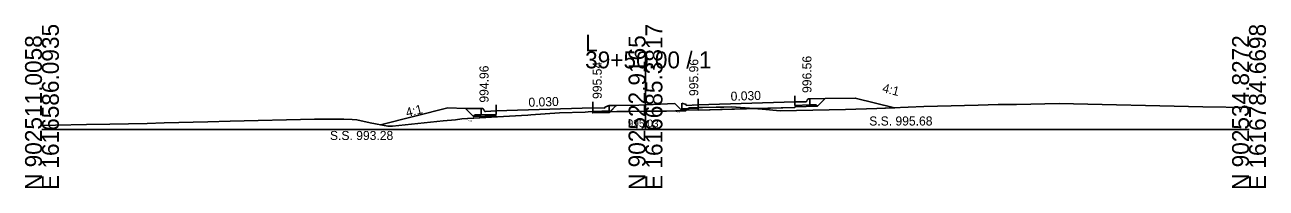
# Model space of a CAD drawing. Extents: x 1009 to 7438, y -1586 to 7964.
# Drawn here: x 3032.1 to 3237.7, y 7414 to 7441.1 of the extents above; entities that cross this region are included whole.
import ezdxf

# ---------------------------------------------------------------- set-up
doc = ezdxf.new("R2010")
doc.units = 0
for name, color, linetype in [('Exist Cross Section Cell', 7, 'Continuous'), ('Exist XS Center Line Elevation Label', 7, 'Continuous'), ('Exist XS Ground Line', 7, 'Continuous'), ('Prop XS Dump Level', 7, 'Continuous'), ('Prop XS Earthwork Shape', 7, 'Continuous'), ('Prop XS EOT Tick Mark', 7, 'Continuous'), ('Prop XS Finish Grade', 7, 'Continuous'), ('Prop XS Finish Grade CurbGutter', 7, 'Continuous'), ('Prop XS Finish Grade Earthwork', 7, 'Continuous'), ('Prop XS Finish Grade Pavement', 7, 'Continuous'), ('Prop XS Hydro Elevations', 7, 'Continuous'), ('Prop XS Pvmt Edge Slope', 7, 'Continuous'), ('Prop XS SE Text', 7, 'Continuous'), ('Prop XS Side Slope Text', 7, 'Continuous'), ('Prop XS SS Elevation Text', 7, 'Continuous'), ('Prop XS Subgrade CurbGutter', 7, 'Continuous'), ('Prop XS Subgrade Earthwork', 7, 'Continuous')]:
    doc.layers.add(name, color=color, linetype=linetype)

msp = doc.modelspace()

# ---------------------------------------------------------------- linework, layer by layer
at = {"layer": 'Exist Cross Section Cell'}
for p, q in [((3134.89, 7423.73), (3134.89, 7436.66)), ((3034.89, 7423.73), (3134.89, 7423.73)), ((3134.89, 7423.73), (3234.89, 7423.73))]:
    msp.add_line(p, q, dxfattribs=at)
at = {"layer": 'Exist XS Ground Line'}
for p, q in [((3141.5, 7426.85), (3142.15, 7427.33)), ((3142.15, 7427.33), (3146.62, 7427.42)), ((3146.62, 7427.42), (3147.17, 7427.43)), ((3147.17, 7427.43), (3147.85, 7427.45)), ((3147.85, 7427.45), (3149.14, 7427.47)), ((3149.14, 7427.47), (3154.22, 7427.1)), ((3168.02, 7427.07), (3173.2, 7427.2)), ((3173.2, 7427.2), (3181.03, 7427.53)), ((3181.03, 7427.53), (3183.27, 7427.61)), ((3183.27, 7427.61), (3190.02, 7427.79)), ((3190.02, 7427.79), (3193.34, 7427.86)), ((3193.34, 7427.86), (3196.34, 7427.88)), ((3196.34, 7427.88), (3203.41, 7428.04)), ((3203.41, 7428.04), (3227.22, 7427.5)), ((3227.22, 7427.5), (3234.89, 7427.37)), ((3062.4, 7425.03), (3066.06, 7425.12)), ((3066.06, 7425.12), (3080.03, 7425.47)), ((3080.03, 7425.47), (3083.82, 7425.45)), ((3083.82, 7425.45), (3084.91, 7425.44)), ((3084.91, 7425.44), (3086.3, 7425.37)), ((3086.3, 7425.37), (3087.07, 7425.33)), ((3087.07, 7425.33), (3089.27, 7424.87)), ((3092.96, 7424.27), (3101.39, 7425.15)), ((3101.39, 7425.15), (3103.42, 7425.36)), ((3103.42, 7425.36), (3104.46, 7425.48)), ((3104.46, 7425.48), (3114.34, 7426.06)), ((3114.34, 7426.06), (3115.39, 7426.13)), ((3115.39, 7426.13), (3115.88, 7426.16)), ((3115.88, 7426.16), (3120.62, 7426.5)), ((3120.62, 7426.5), (3124.89, 7426.63)), ((3124.89, 7426.63), (3125.39, 7426.64)), ((3125.39, 7426.64), (3134.89, 7426.76)), ((3134.89, 7426.76), (3138.39, 7426.8)), ((3138.39, 7426.8), (3139.88, 7426.82)), ((3139.88, 7426.82), (3141.5, 7426.85)), ((3154.22, 7427.1), (3157.2, 7426.84)), ((3157.2, 7426.84), (3168.02, 7427.07)), ((3034.89, 7424.4), (3037.14, 7424.46)), ((3037.14, 7424.46), (3042.26, 7424.58)), ((3042.26, 7424.58), (3046.13, 7424.61)), ((3046.13, 7424.61), (3052.33, 7424.74)), ((3052.33, 7424.74), (3055.12, 7424.84)), ((3055.12, 7424.84), (3062.4, 7425.03)), ((3089.27, 7424.87), (3092.21, 7424.27)), ((3092.21, 7424.27), (3092.96, 7424.27))]:
    msp.add_line(p, q, dxfattribs=at)
at = {"layer": 'Prop XS Dump Level'}
for p, q in [((3110.14, 7426.83), (3126.14, 7427.31)), ((3110.14, 7426.83), (3126.14, 7427.31)), ((3143.64, 7427.83), (3159.64, 7428.31)), ((3143.64, 7427.83), (3159.64, 7428.31))]:
    msp.add_line(p, q, dxfattribs=at)
at = {"layer": 'Prop XS Earthwork Shape'}
for points in [[(3101.39, 7425.15), (3103.42, 7425.36), (3104.46, 7425.48), (3110.14, 7425.81), (3110.14, 7425.91), (3110.14, 7426), (3106.39, 7425.89), (3105.04, 7427.24), (3102.14, 7427.3), (3091, 7424.52), (3092.21, 7424.27), (3092.96, 7424.27)], [(3139.88, 7426.82), (3141.5, 7426.85), (3141.63, 7426.94), (3140.88, 7426.92), (3139.74, 7428.06), (3133.76, 7427.79), (3130.12, 7427.71), (3130.04, 7427.71), (3129.01, 7426.69), (3134.89, 7426.76), (3138.39, 7426.8)], [(3143.64, 7427.25), (3142.14, 7427.21), (3141.98, 7427.2), (3141.63, 7426.94), (3143.64, 7427)], [(3143.64, 7427.25), (3142.14, 7427.21), (3141.98, 7427.2), (3142.15, 7427.33), (3143.64, 7427.36)], [(3143.64, 7427.36), (3143.64, 7427.25), (3143.64, 7427), (3143.64, 7426.92), (3152.89, 7427.19), (3149.14, 7427.47), (3147.85, 7427.45), (3147.17, 7427.43), (3146.62, 7427.42)], [(3173.2, 7427.2), (3176.15, 7427.32), (3169.64, 7428.95), (3164.64, 7428.85), (3163.39, 7427.6), (3159.64, 7427.48), (3159.64, 7427.4), (3152.89, 7427.19), (3154.22, 7427.1), (3157.2, 7426.84), (3168.02, 7427.07)], [(3126.14, 7426.65), (3128.76, 7426.68), (3128.89, 7426.56), (3126.14, 7426.48)], [(3128.76, 7426.68), (3129.01, 7426.69), (3128.89, 7426.56)]]:
    msp.add_lwpolyline(points, close=True, dxfattribs=at)
at = {"layer": 'Prop XS EOT Tick Mark'}
for p, q in [((3159.64, 7428.31), (3159.64, 7429.31)), ((3110.14, 7426.83), (3110.14, 7427.83)), ((3126.14, 7427.31), (3126.14, 7428.31)), ((3143.64, 7427.83), (3143.64, 7428.83))]:
    msp.add_line(p, q, dxfattribs=at)
at = {"layer": 'Prop XS Finish Grade'}
for p, q in [((3107.64, 7427.19), (3105.04, 7427.24)), ((3128.89, 7427.69), (3130.12, 7427.71)), ((3162.14, 7428.79), (3164.64, 7428.85))]:
    msp.add_line(p, q, dxfattribs=at)
at = {"layer": 'Prop XS Finish Grade CurbGutter'}
for p, q in [((3107.64, 7427.19), (3107.89, 7427.19)), ((3107.89, 7427.19), (3108.02, 7427.16)), ((3108.11, 7427.07), (3108.02, 7427.16)), ((3126.14, 7427.31), (3128.14, 7427.27)), ((3128.14, 7427.44), (3128.89, 7427.69)), ((3128.14, 7427.27), (3128.14, 7427.44)), ((3141.65, 7427.86), (3140.9, 7428.11)), ((3141.65, 7427.69), (3141.65, 7427.86)), ((3143.64, 7427.83), (3141.65, 7427.69)), ((3143.64, 7427.83), (3142.89, 7427.78)), ((3159.64, 7428.31), (3161.39, 7428.3)), ((3161.39, 7428.3), (3161.52, 7428.32)), ((3161.52, 7428.32), (3161.61, 7428.41)), ((3161.61, 7428.41), (3161.68, 7428.66)), ((3161.68, 7428.66), (3161.77, 7428.75)), ((3161.89, 7428.79), (3161.77, 7428.75)), ((3162.14, 7428.79), (3161.89, 7428.79)), ((3108.18, 7426.82), (3108.11, 7427.07)), ((3108.27, 7426.73), (3108.18, 7426.82)), ((3108.39, 7426.71), (3108.27, 7426.73)), ((3110.14, 7426.83), (3108.39, 7426.71))]:
    msp.add_line(p, q, dxfattribs=at)
at = {"layer": 'Prop XS Finish Grade Earthwork'}
for p, q in [((3102.14, 7427.3), (3091, 7424.52)), ((3105.04, 7427.24), (3102.14, 7427.3)), ((3130.12, 7427.71), (3133.76, 7427.79)), ((3133.76, 7427.79), (3139.74, 7428.06)), ((3164.64, 7428.85), (3169.64, 7428.95)), ((3169.64, 7428.95), (3176.15, 7427.32))]:
    msp.add_line(p, q, dxfattribs=at)
at = {"layer": 'Prop XS Finish Grade Pavement'}
for p, q in [((3110.14, 7426.83), (3126.14, 7427.31)), ((3143.64, 7427.83), (3159.64, 7428.31))]:
    msp.add_line(p, q, dxfattribs=at)
at = {"layer": 'Prop XS Pvmt Edge Slope'}
for p, q in [((3141.14, 7427.18), (3140.88, 7426.92)), ((3142.14, 7427.21), (3140.9, 7427.17)), ((3162.14, 7427.81), (3163.14, 7427.84)), ((3163.14, 7427.84), (3163.39, 7427.6)), ((3106.64, 7426.14), (3106.39, 7425.89)), ((3107.64, 7426.17), (3106.64, 7426.14)), ((3127.64, 7426.76), (3128.67, 7426.78)), ((3127.64, 7426.76), (3128.89, 7426.78)), ((3128.67, 7426.78), (3128.89, 7426.56))]:
    msp.add_line(p, q, dxfattribs=at)
at = {"layer": 'Prop XS Subgrade CurbGutter'}
for p, q in [((3107.64, 7426.17), (3107.64, 7427.19)), ((3126.14, 7427.31), (3126.14, 7426.73)), ((3128.89, 7426.78), (3128.89, 7427.69)), ((3140.9, 7427.17), (3140.9, 7428.11)), ((3143.64, 7427.25), (3142.14, 7427.21)), ((3143.64, 7427.83), (3143.64, 7427.25)), ((3159.64, 7428.31), (3159.64, 7427.73)), ((3159.64, 7427.73), (3162.14, 7427.81)), ((3162.14, 7427.81), (3162.14, 7428.79)), ((3110.14, 7426.25), (3107.64, 7426.17)), ((3110.14, 7426.83), (3110.14, 7426.25)), ((3126.14, 7426.73), (3127.64, 7426.76))]:
    msp.add_line(p, q, dxfattribs=at)
at = {"layer": 'Prop XS Subgrade Earthwork'}
for p, q in [((3106.39, 7425.89), (3105.04, 7427.24)), ((3128.89, 7426.56), (3130.04, 7427.71)), ((3140.88, 7426.92), (3139.74, 7428.06)), ((3143.64, 7426.92), (3159.64, 7427.4)), ((3143.64, 7426.92), (3143.64, 7427.36)), ((3143.64, 7426.92), (3143.64, 7427.36)), ((3159.64, 7427.48), (3163.39, 7427.6)), ((3159.64, 7427.4), (3159.64, 7427.48)), ((3163.39, 7427.6), (3164.64, 7428.85)), ((3110.14, 7426), (3106.39, 7425.89)), ((3110.14, 7425.91), (3110.14, 7426)), ((3110.14, 7425.91), (3110.14, 7425.81)), ((3126.14, 7426.48), (3126.14, 7426.65)), ((3126.14, 7426.48), (3128.89, 7426.56)), ((3143.64, 7427), (3140.88, 7426.92)), ((3143.64, 7426.92), (3143.64, 7427))]:
    msp.add_line(p, q, dxfattribs=at)

# ---------------------------------------------------------------- texts
at = {"layer": 'Exist Cross Section Cell'}
for s, p in [('E 1616586.0935', (3037.69, 7413.73)), ('E 1616685.3817', (3137.69, 7413.73)), ('E 1616784.6698', (3237.69, 7413.73)), ('N 902511.0058', (3034.89, 7413.73)), ('N 902522.9165', (3134.89, 7413.73)), ('N 902534.8272', (3234.89, 7413.73))]:
    msp.add_text(s, height=2.8, rotation=90, dxfattribs=at).set_placement(p)
for s, p in [('L', (3124.89, 7436.66)), ('39+50.00 / 1', (3124.89, 7433.86))]:
    msp.add_text(s, height=2.8, dxfattribs=at).set_placement(p)
at = {"layer": 'Exist XS Center Line Elevation Label'}
msp.add_text('995.03', height=1.25, dxfattribs=at).set_placement((3131.94, 7424.13))
at = {"layer": 'Prop XS Dump Level'}
for p in [(3105.43, 7425.02), (3139.89, 7426.52), (3139.89, 7426.52), (3139.89, 7426.52)]:
    msp.add_text('Eop', height=0.3, dxfattribs=at).set_placement(p)
at = {"layer": 'Prop XS Hydro Elevations'}
for s, p in [('996.56', (3162.39, 7429.79)), ('994.96', (3108.89, 7428.19)), ('995.54', (3127.64, 7428.8)), ('995.96', (3143.64, 7429.28))]:
    msp.add_text(s, height=1.5, rotation=90, dxfattribs=at).set_placement(p)
at = {"layer": 'Prop XS SE Text'}
for p in [(3149.02, 7428.49), (3115.52, 7427.49)]:
    msp.add_text('0.030', height=1.5, rotation=1.7184, dxfattribs=at).set_placement(p)
at = {"layer": 'Prop XS Side Slope Text'}
for rotation, p in [(345.9638, (3174.03, 7429.94)), (14.0362, (3095.37, 7425.78))]:
    msp.add_text('4:1', height=1.5, rotation=rotation, dxfattribs=at).set_placement(p)
at = {"layer": 'Prop XS SS Elevation Text'}
for s, p in [('S.S. 995.68', (3171.96, 7424.4)), ('S.S. 993.28', (3082.61, 7422))]:
    msp.add_text(s, height=1.5, dxfattribs=at).set_placement(p)

doc.saveas('drawing.dxf')
